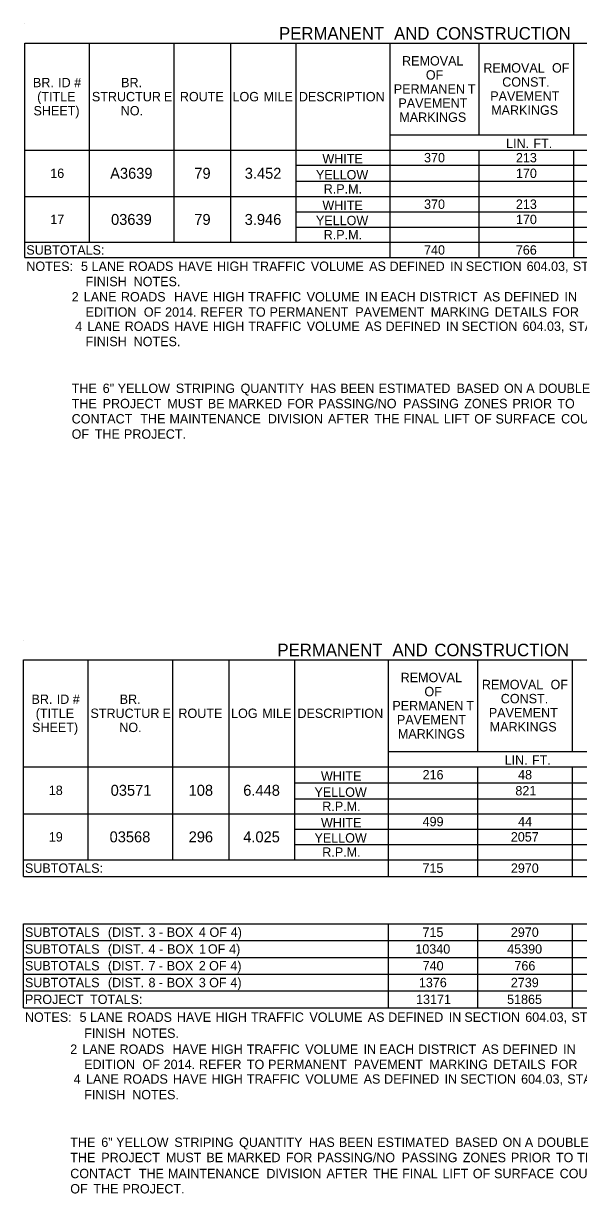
# Model space of a CAD drawing. Extents: x 540541 to 1930787, y -1948574 to 596640.
# Drawn here: x 542612 to 542967, y -1948453 to -1947705 of the extents above; entities that cross this region are included whole.
import ezdxf

# ---------------------------------------------------------------- set-up
doc = ezdxf.new("R2010")
doc.units = 0
doc.layers.add('Default', color=7, linetype='Continuous')
doc.layers.add('R_Border', color=7, linetype='Continuous')

msp = doc.modelspace()

# ---------------------------------------------------------------- linework, layer by layer
at = {"layer": 'Default'}
for p, q in [((542613.14, -1947717.57), (543373.15, -1947717.57)), ((542613.14, -1947854.56), (542613.14, -1947717.57)), ((542654.57, -1947844.81), (542654.57, -1947717.57)), ((542708.69, -1947844.81), (542708.69, -1947717.57)), ((542744.76, -1947844.81), (542744.76, -1947717.57)), ((542786.69, -1947844.81), (542786.69, -1947717.57)), ((542846.65, -1947854.56), (542846.65, -1947717.57)), ((542903.69, -1947776.07), (542903.69, -1947717.57)), ((542964.14, -1947776.07), (542964.14, -1947717.57)), ((542846.65, -1947776.07), (543373.15, -1947776.07)), ((542613.14, -1947785.82), (543373.15, -1947785.82)), ((542786.69, -1947785.82), (543373.15, -1947785.82)), ((542786.69, -1947844.81), (542786.69, -1947785.82)), ((542846.65, -1947805.81), (542846.65, -1947785.82)), ((542903.69, -1947854.56), (542903.69, -1947785.82)), ((542903.69, -1947854.56), (542903.69, -1947785.82)), ((542964.14, -1947854.56), (542964.14, -1947785.82)), ((542964.14, -1947854.56), (542964.14, -1947785.82)), ((542786.69, -1947795.57), (543373.15, -1947795.57)), ((542786.69, -1947805.81), (543373.15, -1947805.81)), ((542613.14, -1947815.56), (543373.15, -1947815.56)), ((542786.69, -1947815.56), (543373.15, -1947815.56)), ((542846.65, -1947835.06), (542846.65, -1947815.56)), ((542786.69, -1947825.31), (543373.15, -1947825.31)), ((542786.69, -1947835.06), (543373.15, -1947835.06)), ((542613.14, -1947844.81), (543373.15, -1947844.81)), ((542846.65, -1947854.56), (542846.65, -1947844.81)), ((542613.14, -1947854.56), (543373.15, -1947854.56)), ((542612.22, -1948111.69), (543372.23, -1948111.69)), ((542612.22, -1948250.14), (542612.22, -1948111.69)), ((542653.66, -1948239.42), (542653.66, -1948111.69)), ((542707.77, -1948239.42), (542707.77, -1948111.69)), ((542743.85, -1948239.42), (542743.85, -1948111.69)), ((542785.77, -1948239.42), (542785.77, -1948111.69)), ((542845.73, -1948250.14), (542845.73, -1948111.69)), ((542902.77, -1948170.19), (542902.77, -1948111.69)), ((542963.22, -1948170.19), (542963.22, -1948111.69)), ((542845.73, -1948170.19), (543372.23, -1948170.19)), ((542612.22, -1948179.94), (543372.23, -1948179.94)), ((542785.77, -1948179.94), (543287.41, -1948179.94)), ((542785.77, -1948239.42), (542785.77, -1948179.94)), ((542845.73, -1948200.42), (542845.73, -1948179.94)), ((542902.77, -1948250.14), (542902.77, -1948179.94)), ((542902.77, -1948250.14), (542902.77, -1948179.94)), ((542963.22, -1948250.14), (542963.22, -1948179.94)), ((542963.22, -1948250.14), (542963.22, -1948179.94)), ((542785.77, -1948190.18), (543372.23, -1948190.18)), ((542785.77, -1948200.42), (543372.23, -1948200.42)), ((542612.22, -1948210.17), (543372.23, -1948210.17)), ((542785.77, -1948210.17), (543287.41, -1948210.17)), ((542845.73, -1948229.67), (542845.73, -1948210.17)), ((542785.77, -1948219.92), (543372.23, -1948219.92)), ((542785.77, -1948229.67), (543372.23, -1948229.67)), ((542612.22, -1948239.42), (543372.23, -1948239.42)), ((542845.73, -1948250.14), (542845.73, -1948239.42)), ((542612.22, -1948250.14), (543372.23, -1948250.14)), ((542612.22, -1948280.37), (543372.23, -1948280.37)), ((542612.22, -1948280.37), (543372.23, -1948280.37)), ((542612.22, -1948333.99), (542612.22, -1948280.37)), ((542845.73, -1948291.09), (542845.73, -1948280.37)), ((542845.73, -1948333.99), (542845.73, -1948280.37)), ((542902.77, -1948291.09), (542902.77, -1948280.37)), ((542902.77, -1948333.99), (542902.77, -1948280.37)), ((542963.22, -1948291.09), (542963.22, -1948280.37)), ((542963.22, -1948333.99), (542963.22, -1948280.37)), ((542612.22, -1948291.09), (543372.23, -1948291.09)), ((542612.22, -1948301.82), (543372.23, -1948301.82)), ((542845.73, -1948333.99), (542845.73, -1948301.82)), ((542902.77, -1948333.99), (542902.77, -1948301.82)), ((542963.22, -1948323.27), (542963.22, -1948301.82)), ((542612.22, -1948312.54), (543372.23, -1948312.54)), ((542612.22, -1948323.27), (543372.23, -1948323.27)), ((542612.22, -1948333.99), (543372.23, -1948333.99))]:
    msp.add_line(p, q, dxfattribs=at)
at = {"layer": 'R_Border'}
for p, q in [((542613.14, -1947704.9), (542613.14, -1947704.9)), ((542612.22, -1948099.02), (542612.22, -1948099.02))]:
    msp.add_line(p, q, dxfattribs=at)

# ---------------------------------------------------------------- texts
at = {"layer": 'Default'}
for s, height, p in [('PERMANENT', 8, (542775.69, -1947715.24)), (' AND', 8, (542846.26, -1947715.24)), (' CONSTRUCTION', 8, (542873.03, -1947715.24)), ('REMOVAL', 6, (542854.33, -1947731.82)), ('REMOVAL', 6, (542906.29, -1947736.32)), (' OF', 6, (542947.96, -1947736.32)), ('BR.', 6, (542618.33, -1947745.7)), (' ID', 6, (542632.19, -1947745.7)), (' #', 6, (542642.49, -1947745.7)), ('BR.', 6, (542674.7, -1947745.7)), ('OF', 6, (542869.54, -1947740.82)), ('CONST.', 6, (542918.36, -1947745.32)), ('PERMANEN', 6, (542849.04, -1947749.82)), ('T', 6, (542896.35, -1947749.82)), ('(TITLE', 6, (542621.03, -1947754.7)), ('STRUCTUR', 6, (542656.01, -1947754.7)), ('E', 6, (542702.08, -1947754.7)), ('ROUTE', 6, (542712.26, -1947754.7)), ('LOG', 6, (542745.93, -1947754.7)), (' MILE', 6, (542763.58, -1947754.7)), ('DESCRIPTION', 6, (542788.36, -1947754.7)), ('PAVEMENT', 6, (542851.96, -1947758.82)), ('PAVEMENT', 6, (542910.71, -1947754.32)), ('SHEET)', 6, (542618.7, -1947763.7)), ('NO.', 6, (542674.47, -1947763.7)), ('MARKINGS', 6, (542852.55, -1947767.82)), ('MARKINGS', 6, (542911.3, -1947763.32)), ('LIN.', 6, (542920.83, -1947784.62)), (' FT.', 6, (542936.09, -1947784.62)), ('WHITE', 6, (542803.39, -1947794.37)), ('370', 6, (542868.38, -1947793.7)), ('213', 6, (542927.11, -1947793.7)), ('16', 6, (542629.39, -1947803.69)), ('A3639', 7, (542667.71, -1947804.19)), ('79', 7, (542721.5, -1947804.19)), ('3.452', 7, (542753.75, -1947804.19)), ('YELLOW', 6, (542799.25, -1947804.61)), ('170', 6, (542927.12, -1947803.69)), ('R.P.M.', 6, (542804.23, -1947813.69)), ('WHITE', 6, (542803.39, -1947824.11)), ('370', 6, (542868.38, -1947823.44)), ('213', 6, (542927.11, -1947823.44)), ('17', 6, (542629.39, -1947833.19)), ('03639', 7, (542668.26, -1947833.69)), ('79', 7, (542721.5, -1947833.69)), ('3.946', 7, (542753.72, -1947833.69)), ('YELLOW', 6, (542799.25, -1947833.86)), ('170', 6, (542927.12, -1947833.19)), ('R.P.M.', 6, (542804.23, -1947842.94)), ('SUBTOTALS:', 6, (542614.11, -1947852.69)), ('740', 6, (542868.38, -1947852.69)), ('766', 6, (542927.07, -1947852.69)), ('NOTES:', 6, (542614.11, -1947863.11)), ('  5', 6, (542644.59, -1947863.11)), (' LANE', 6, (542653.57, -1947863.11)), (' ROADS', 6, (542677.35, -1947863.11)), (' HAVE', 6, (542709.06, -1947863.11)), (' HIGH', 6, (542733.77, -1947863.11)), (' TRAFFIC', 6, (542756.38, -1947863.11)), (' VOLUME', 6, (542793.77, -1947863.11)), (' AS', 6, (542831.06, -1947863.11)), (' DEFINED', 6, (542844.13, -1947863.11)), (' IN', 6, (542882.81, -1947863.11)), (' SECTION', 6, (542892.84, -1947863.11)), (' 604.03,', 6, (542931.75, -1947863.11)), (' STANDARD', 6, (542961.28, -1947863.11)), ('                 FINISH', 6, (542614.11, -1947872.86)), (' NOTES.', 6, (542680.49, -1947872.86)), ('             2', 6, (542614.11, -1947882.61)), (' LANE', 6, (542648.59, -1947882.61)), (' ROADS', 6, (542672.37, -1947882.61)), ('  HAVE', 6, (542704.08, -1947882.61)), (' HIGH', 6, (542731.12, -1947882.61)), (' TRAFFIC', 6, (542753.73, -1947882.61)), (' VOLUME', 6, (542791.12, -1947882.61)), (' IN', 6, (542828.4, -1947882.61)), (' EACH', 6, (542838.43, -1947882.61)), (' DISTRICT', 6, (542863.37, -1947882.61)), (' AS', 6, (542904.19, -1947882.61)), (' DEFINED', 6, (542917.26, -1947882.61)), (' IN', 6, (542955.94, -1947882.61)), ('                 EDITION', 6, (542614.11, -1947892.36)), (' OF', 6, (542687, -1947892.36)), (' 2014.', 6, (542700.59, -1947892.36)), (' REFER', 6, (542723.15, -1947892.36)), (' TO', 6, (542753.78, -1947892.36)), (' PERMANENT', 6, (542767.38, -1947892.36)), (' PAVEMENT', 6, (542822.18, -1947892.36)), (' MARKING', 6, (542870.46, -1947892.36)), (' DETAILS', 6, (542911.39, -1947892.36)), (' FOR', 6, (542948.22, -1947892.36)), ('              4', 6, (542614.11, -1947901.44)), (' LANE', 6, (542650.95, -1947901.44)), (' ROADS', 6, (542674.73, -1947901.44)), (' HAVE', 6, (542706.44, -1947901.44)), (' HIGH', 6, (542731.15, -1947901.44)), (' TRAFFIC', 6, (542753.76, -1947901.44)), (' VOLUME', 6, (542791.15, -1947901.44)), (' AS', 6, (542828.44, -1947901.44)), (' DEFINED', 6, (542841.51, -1947901.44)), (' IN', 6, (542880.19, -1947901.44)), (' SECTION', 6, (542890.22, -1947901.44)), (' 604.03,', 6, (542929.13, -1947901.44)), (' STANDARD', 6, (542958.66, -1947901.44)), ('                 FINISH', 6, (542614.11, -1947911.19)), (' NOTES.', 6, (542680.49, -1947911.19)), (' 6"', 6, (542660.69, -1947941.11)), (' YELLOW', 6, (542670.27, -1947941.11)), (' STRIPING', 6, (542707.44, -1947941.11)), (' QUANTITY', 6, (542748.83, -1947941.11)), (' HAS', 6, (542793.49, -1947941.11)), (' ESTIMATED', 6, (542837.09, -1947941.11)), (' BASED', 6, (542886.95, -1947941.11)), (' ON', 6, (542917.26, -1947941.11)), (' DOUBLE', 6, (542939.41, -1947941.11)), ('             THE', 6, (542614.11, -1947941.11)), (' BEEN', 6, (542812.62, -1947941.11)), (' A', 6, (542931.48, -1947941.11)), ('             THE', 6, (542614.11, -1947950.86)), (' PROJECT', 6, (542660.69, -1947950.86)), (' MUST', 6, (542701.99, -1947950.86)), (' BE', 6, (542727.9, -1947950.86)), (' MARKED', 6, (542740.96, -1947950.86)), (' FOR', 6, (542778.71, -1947950.86)), (' PASSING/NO', 6, (542798.63, -1947950.86)), (' PASSING', 6, (542852.76, -1947950.86)), (' ZONES', 6, (542891.84, -1947950.86)), (' PRIOR', 6, (542922.61, -1947950.86)), (' TO', 6, (542951.37, -1947950.86)), ('             CONTACT', 6, (542614.11, -1947960.61)), (' THE', 6, (542684.73, -1947960.61)), (' MAINTENANCE', 6, (542703.38, -1947960.61)), (' DIVISION', 6, (542766.28, -1947960.61)), (' AFTER', 6, (542804.72, -1947960.61)), (' THE', 6, (542834.42, -1947960.61)), (' FINAL', 6, (542853.07, -1947960.61)), (' LIFT', 6, (542878.86, -1947960.61)), (' OF', 6, (542898.25, -1947960.61)), (' SURFACE', 6, (542911.84, -1947960.61)), (' COURSE', 6, (542953.78, -1947960.61)), ('             OF', 6, (542614.11, -1947970.36)), (' THE', 6, (542655.63, -1947970.36)), (' PROJECT.', 6, (542674.28, -1947970.36)), ('PERMANENT', 8, (542774.66, -1948109.35)), (' AND', 8, (542845.23, -1948109.35)), (' CONSTRUCTION', 8, (542872, -1948109.35)), ('REMOVAL', 6, (542853.42, -1948125.94)), ('OF', 6, (542868.63, -1948134.94)), ('REMOVAL', 6, (542905.37, -1948130.44)), (' OF', 6, (542947.04, -1948130.44)), ('BR.', 6, (542617.42, -1948139.82)), (' ID', 6, (542631.28, -1948139.82)), (' #', 6, (542641.57, -1948139.82)), ('BR.', 6, (542673.79, -1948139.82)), ('CONST.', 6, (542917.45, -1948139.44)), ('(TITLE', 6, (542620.11, -1948148.82)), ('STRUCTUR', 6, (542655.09, -1948148.82)), ('E', 6, (542701.16, -1948148.82)), ('ROUTE', 6, (542711.34, -1948148.82)), ('LOG', 6, (542745.01, -1948148.82)), (' MILE', 6, (542762.67, -1948148.82)), ('DESCRIPTION', 6, (542787.44, -1948148.82)), ('PERMANEN', 6, (542848.12, -1948143.94)), ('T', 6, (542895.43, -1948143.94)), ('PAVEMENT', 6, (542909.79, -1948148.44)), ('SHEET)', 6, (542617.79, -1948157.82)), ('NO.', 6, (542673.55, -1948157.82)), ('PAVEMENT', 6, (542851.05, -1948152.94)), ('MARKINGS', 6, (542910.38, -1948157.44)), ('MARKINGS', 6, (542851.64, -1948161.94)), ('LIN.', 6, (542919.91, -1948178.74)), (' FT.', 6, (542935.17, -1948178.74)), ('WHITE', 6, (542802.47, -1948188.98)), ('216', 6, (542867.45, -1948188.06)), ('48', 6, (542928.52, -1948188.06)), ('18', 6, (542628.47, -1948198.05)), ('03571', 7, (542668.02, -1948198.55)), ('108', 7, (542717.87, -1948198.55)), ('6.448', 7, (542752.79, -1948198.55)), ('YELLOW', 6, (542798.33, -1948199.22)), ('821', 6, (542926.78, -1948198.3)), ('R.P.M.', 6, (542803.31, -1948208.29)), ('WHITE', 6, (542802.47, -1948218.72)), ('499', 6, (542867.45, -1948218.04)), ('44', 6, (542928.54, -1948218.04)), ('19', 6, (542628.47, -1948227.79)), ('03568', 7, (542667.34, -1948228.29)), ('296', 7, (542717.88, -1948228.29)), ('4.025', 7, (542752.77, -1948228.29)), ('YELLOW', 6, (542798.33, -1948228.47)), ('2057', 6, (542923.87, -1948227.79)), ('R.P.M.', 6, (542803.31, -1948237.54)), ('SUBTOTALS:', 6, (542613.2, -1948247.78)), ('2970', 6, (542923.88, -1948247.78)), ('715', 6, (542867.39, -1948247.78)), ('SUBTOTALS', 6, (542613.2, -1948288.73)), (' (DIST.', 6, (542664.02, -1948288.73)), (' 3', 6, (542689.99, -1948288.73)), (' -', 6, (542696.62, -1948288.73)), (' BOX', 6, (542701.67, -1948288.73)), (' 4', 6, (542722.16, -1948288.73)), (' OF', 6, (542728.96, -1948288.73)), (' 4)', 6, (542742.54, -1948288.73)), ('715', 6, (542867.39, -1948288.73)), ('2970', 6, (542923.88, -1948288.73)), ('SUBTOTALS', 6, (542613.2, -1948299.45)), (' (DIST.', 6, (542664.02, -1948299.45)), (' 4', 6, (542689.99, -1948299.45)), (' BOX', 6, (542701.84, -1948299.45)), (' 1', 6, (542722.33, -1948299.45)), (' OF', 6, (542727.96, -1948299.45)), (' 4)', 6, (542741.54, -1948299.45)), ('10340', 6, (542862.81, -1948299.45)), ('45390', 6, (542921.55, -1948299.45)), (' -', 6, (542696.79, -1948299.45)), ('SUBTOTALS', 6, (542613.2, -1948310.18)), (' (DIST.', 6, (542664.02, -1948310.18)), (' 7', 6, (542689.99, -1948310.18)), (' -', 6, (542696.61, -1948310.18)), (' BOX', 6, (542701.67, -1948310.18)), (' 2', 6, (542722.15, -1948310.18)), (' OF', 6, (542728.72, -1948310.18)), (' 4)', 6, (542742.3, -1948310.18)), ('740', 6, (542867.47, -1948310.18)), ('766', 6, (542926.16, -1948310.18)), ('SUBTOTALS', 6, (542613.2, -1948320.9)), (' (DIST.', 6, (542664.02, -1948320.9)), (' 8', 6, (542689.99, -1948320.9)), (' BOX', 6, (542701.66, -1948320.9)), (' 3', 6, (542722.15, -1948320.9)), (' OF', 6, (542728.77, -1948320.9)), (' 4)', 6, (542742.36, -1948320.9)), ('1376', 6, (542865.08, -1948320.9)), ('2739', 6, (542923.87, -1948320.9)), (' -', 6, (542696.6, -1948320.9)), ('PROJECT', 6, (542613.2, -1948331.63)), (' TOTALS:', 6, (542652.62, -1948331.63)), ('13171', 6, (542863.28, -1948331.63)), ('51865', 6, (542921.47, -1948331.63)), ('NOTES:', 6, (542613.2, -1948343.03)), ('  5', 6, (542643.68, -1948343.03)), (' LANE', 6, (542652.66, -1948343.03)), (' ROADS', 6, (542676.44, -1948343.03)), (' HAVE', 6, (542708.15, -1948343.03)), (' HIGH', 6, (542732.86, -1948343.03)), (' TRAFFIC', 6, (542755.47, -1948343.03)), (' VOLUME', 6, (542792.86, -1948343.03)), (' AS', 6, (542830.14, -1948343.03)), (' DEFINED', 6, (542843.22, -1948343.03)), (' IN', 6, (542881.9, -1948343.03)), (' SECTION', 6, (542891.92, -1948343.03)), (' 604.03,', 6, (542930.83, -1948343.03)), (' STANDARD', 6, (542960.37, -1948343.03)), ('                 FINISH', 6, (542613.2, -1948353.27)), (' NOTES.', 6, (542679.57, -1948353.27)), ('             2', 6, (542613.2, -1948363.5)), (' LANE', 6, (542647.67, -1948363.5)), (' ROADS', 6, (542671.45, -1948363.5)), ('  HAVE', 6, (542703.16, -1948363.5)), (' HIGH', 6, (542730.2, -1948363.5)), (' TRAFFIC', 6, (542752.81, -1948363.5)), (' VOLUME', 6, (542790.2, -1948363.5)), (' IN', 6, (542827.49, -1948363.5)), (' EACH', 6, (542837.51, -1948363.5)), (' DISTRICT', 6, (542862.46, -1948363.5)), (' AS', 6, (542903.27, -1948363.5)), (' DEFINED', 6, (542916.35, -1948363.5)), (' IN', 6, (542955.03, -1948363.5)), ('                 EDITION', 6, (542613.2, -1948373.25)), (' OF', 6, (542686.08, -1948373.25)), (' 2014.', 6, (542699.67, -1948373.25)), (' REFER', 6, (542722.24, -1948373.25)), (' TO', 6, (542752.87, -1948373.25)), (' PERMANENT', 6, (542766.46, -1948373.25)), (' PAVEMENT', 6, (542821.26, -1948373.25)), (' MARKING', 6, (542869.55, -1948373.25)), (' DETAILS', 6, (542910.48, -1948373.25)), (' FOR', 6, (542947.31, -1948373.25)), ('              4', 6, (542613.2, -1948382.57)), (' LANE', 6, (542650.04, -1948382.57)), (' ROADS', 6, (542673.82, -1948382.57)), (' HAVE', 6, (542705.52, -1948382.57)), (' HIGH', 6, (542730.24, -1948382.57)), (' TRAFFIC', 6, (542752.85, -1948382.57)), (' VOLUME', 6, (542790.24, -1948382.57)), (' AS', 6, (542827.52, -1948382.57)), (' DEFINED', 6, (542840.6, -1948382.57)), (' IN', 6, (542879.28, -1948382.57)), (' SECTION', 6, (542889.3, -1948382.57)), (' 604.03,', 6, (542928.21, -1948382.57)), (' STANDARD', 6, (542957.75, -1948382.57)), ('                 FINISH', 6, (542613.2, -1948392.57)), (' NOTES.', 6, (542679.57, -1948392.57)), ('             THE', 6, (542613.2, -1948422.98)), (' 6"', 6, (542659.78, -1948422.98)), (' YELLOW', 6, (542669.35, -1948422.98)), (' STRIPING', 6, (542706.52, -1948422.98)), (' QUANTITY', 6, (542747.92, -1948422.98)), (' HAS', 6, (542792.57, -1948422.98)), (' BEEN', 6, (542811.7, -1948422.98)), (' ESTIMATED', 6, (542836.18, -1948422.98)), (' BASED', 6, (542886.04, -1948422.98)), (' ON', 6, (542916.34, -1948422.98)), (' A', 6, (542930.56, -1948422.98)), (' DOUBLE', 6, (542938.5, -1948422.98)), ('             THE', 6, (542613.2, -1948432.73)), (' PROJECT', 6, (542659.78, -1948432.73)), (' MUST', 6, (542701.07, -1948432.73)), (' BE', 6, (542726.98, -1948432.73)), (' MARKED', 6, (542740.05, -1948432.73)), (' FOR', 6, (542777.8, -1948432.73)), (' PASSING/NO', 6, (542797.71, -1948432.73)), (' PASSING', 6, (542851.84, -1948432.73)), (' ZONES', 6, (542890.92, -1948432.73)), (' PRIOR', 6, (542921.69, -1948432.73)), (' TO', 6, (542950.46, -1948432.73)), (' THE', 6, (542964.06, -1948432.73)), ('             CONTACT', 6, (542613.2, -1948442.97)), (' THE', 6, (542683.81, -1948442.97)), (' MAINTENANCE', 6, (542702.46, -1948442.97)), (' DIVISION', 6, (542765.36, -1948442.97)), (' AFTER', 6, (542803.81, -1948442.97)), (' THE', 6, (542833.51, -1948442.97)), (' FINAL', 6, (542852.15, -1948442.97)), (' LIFT', 6, (542877.94, -1948442.97)), (' OF', 6, (542897.33, -1948442.97)), (' SURFACE', 6, (542910.92, -1948442.97)), (' COURSE', 6, (542952.86, -1948442.97)), ('             OF', 6, (542613.2, -1948452.72)), (' THE', 6, (542654.72, -1948452.72)), (' PROJECT.', 6, (542673.37, -1948452.72))]:
    msp.add_text(s, height=height, dxfattribs=at).set_placement(p)

doc.saveas('drawing.dxf')
